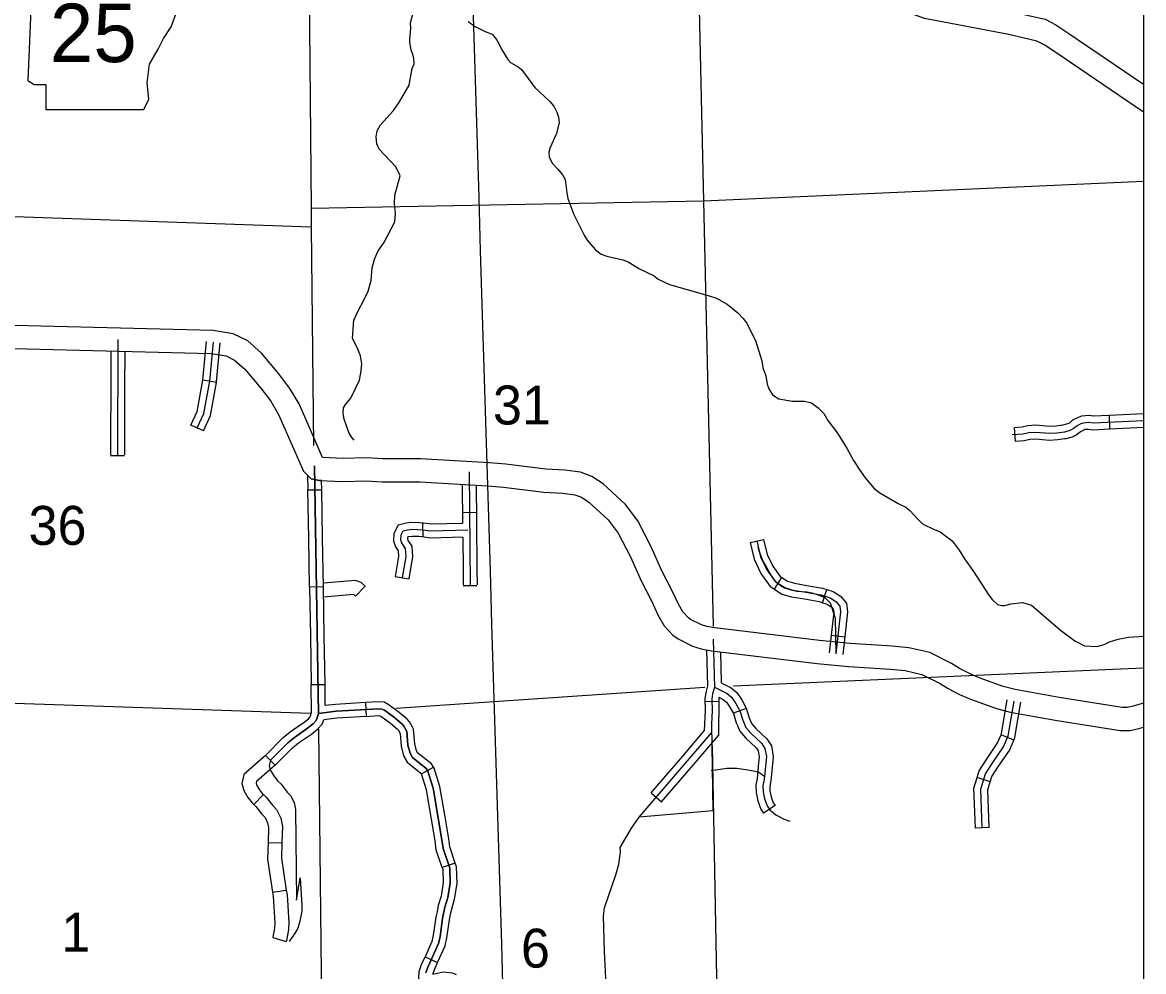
# Model space of a CAD drawing. Extents: x 1212896 to 1368412, y 378476 to 478763.
# Drawn here: x 1307154 to 1319317, y 403202 to 413498 of the extents above; entities that cross this region are included whole.
import ezdxf

# ---------------------------------------------------------------- set-up
doc = ezdxf.new("R2010")
doc.units = 0
for name, color, linetype in [('1', 7, 'Continuous'), ('Level 10', 7, 'Continuous'), ('Level 21', 7, 'Continuous'), ('Level 31', 7, 'Continuous'), ('Level 32', 7, 'Continuous'), ('Level 35', 7, 'Continuous'), ('Level 4', 7, 'Continuous'), ('Level 45', 7, 'Continuous'), ('Level 5', 7, 'Continuous'), ('Level 60', 7, 'Continuous')]:
    doc.layers.add(name, color=color, linetype=linetype)

msp = doc.modelspace()

# ---------------------------------------------------------------- linework, layer by layer
at = {"layer": '1'}
msp.add_lwpolyline([(1257400, 437504), (1319317, 437504), (1319317, 388319), (1257400, 388319)], close=True, dxfattribs=at)
at = {"layer": 'Level 10'}
for points in [[(1312881, 415815), (1314205, 414413), (1314294, 414326), (1314300, 414323), (1314959, 414335), (1315070, 414315), (1315316, 414244), (1316344, 414016), (1316809, 413855), (1317007, 413781), (1317906, 413611), (1318249, 413533), (1318366, 413471), (1318506, 413380), (1319317, 412828)], [(1319317, 412525), (1318367, 413172), (1318239, 413255), (1318161, 413296), (1317855, 413366), (1316940, 413540), (1316725, 413620), (1316276, 413775), (1315255, 414002), (1315013, 414071), (1314939, 414084), (1314254, 414072), (1314154, 414112), (1314027, 414238), (1312699, 415644)], [(1312217, 408722), (1311473, 408764), (1311065, 408764), (1310887, 408774), (1310631, 408767), (1310410, 408779), (1310156, 409360), (1310056, 409529), (1309937, 409686), (1309747, 409910), (1309598, 410045), (1309442, 410121), (1309225, 410157), (1306346, 410229), (1305872, 410234), (1302228, 410310)], [(1302110, 410062), (1305869, 409984), (1306341, 409979), (1309201, 409908), (1309365, 409880), (1309456, 409836), (1309567, 409736), (1309742, 409530), (1309848, 409390), (1309933, 409246), (1310203, 408629), (1310286, 408547), (1310378, 408530), (1310628, 408517), (1310884, 408524), (1311058, 408514), (1311466, 408514), (1312198, 408472)], [(1319317, 406113), (1319204, 406080), (1319143, 406067), (1319084, 406066), (1318400, 406176), (1317924, 406262), (1317793, 406295), (1317533, 406389), (1317429, 406434), (1317320, 406490), (1317232, 406545), (1316997, 406663), (1316772, 406715), (1316591, 406733), (1316135, 406762), (1315801, 406792), (1314667, 406930), (1314578, 406945), (1314520, 406964), (1314402, 407023), (1314379, 407040), (1314318, 407104), (1314270, 407186), (1314208, 407324), (1314090, 407550), (1313976, 407808), (1313830, 408091), (1313695, 408270), (1313454, 408493), (1313333, 408572), (1313208, 408619), (1313038, 408641), (1312833, 408651), (1312399, 408705), (1312217, 408722)], [(1312198, 408472), (1312372, 408456), (1312811, 408402), (1313016, 408391), (1313147, 408374), (1313219, 408348), (1313300, 408295), (1313509, 408101), (1313618, 407957), (1313750, 407700), (1313865, 407442), (1313983, 407215), (1314048, 407071), (1314117, 406953), (1314212, 406853), (1314269, 406810), (1314425, 406731), (1314519, 406702), (1314631, 406683), (1315775, 406543), (1316116, 406513), (1316571, 406484), (1316731, 406468), (1316912, 406426), (1317109, 406327), (1317196, 406273), (1317322, 406208), (1317441, 406156), (1317720, 406056), (1317871, 406018), (1318358, 405929), (1319065, 405816), (1319171, 405817), (1319265, 405838), (1319317, 405853)]]:
    msp.add_lwpolyline(points, dxfattribs=at)
at = {"layer": 'Level 21'}
for p, q in [((1307247, 413638), (1307213, 412868)), ((1308769, 413452), (1308820, 413587)), ((1308685, 413325), (1308769, 413452)), ((1308626, 413207), (1308685, 413325)), ((1308533, 413046), (1308626, 413207)), ((1308507, 412843), (1308533, 413046)), ((1307213, 412868), (1307281, 412826)), ((1307281, 412826), (1307408, 412826)), ((1307408, 412826), (1307408, 412555)), ((1308524, 412665), (1308507, 412843)), ((1308473, 412555), (1308524, 412665)), ((1307408, 412555), (1308473, 412555))]:
    msp.add_line(p, q, dxfattribs=at)
at = {"layer": 'Level 31'}
for p, q in [((1310251, 408427), (1310401, 408429)), ((1310419, 407374), (1310269, 407371)), ((1310269, 407371), (1310269, 407371)), ((1310287, 406315), (1310437, 406318)), ((1310875, 406121), (1310884, 405971)), ((1311252, 405784), (1311252, 405784)), ((1309897, 405441), (1309791, 405547)), ((1311483, 405346), (1311613, 405420)), ((1311850, 404380), (1311708, 404332)), ((1311522, 403362), (1311659, 403301))]:
    msp.add_line(p, q, dxfattribs=at)
for points in [[(1310367, 406002), (1310322, 408688)], [(1310248, 408584), (1310251, 408427)], [(1310399, 408529), (1310378, 408530), (1310286, 408547), (1310248, 408584)], [(1310401, 408429), (1310399, 408529)], [(1310260, 407899), (1310251, 408427)], [(1310410, 407902), (1310401, 408429)], [(1310269, 407371), (1310260, 407899)], [(1310419, 407374), (1310410, 407902)], [(1310269, 407371), (1310278, 406843)], [(1310428, 406846), (1310419, 407374)], [(1310278, 406843), (1310287, 406315)], [(1310437, 406318), (1310428, 406846)], [(1310196, 405897), (1310257, 405944), (1310275, 405964), (1310292, 406014), (1310287, 406315)], [(1310440, 406087), (1310437, 406318)], [(1311382, 405860), (1311353, 405910), (1311327, 405940), (1311241, 406014), (1311121, 406101), (1311077, 406123), (1311022, 406130), (1310875, 406121)], [(1311532, 403189), (1311554, 403250), (1311667, 403505), (1311686, 403584), (1311713, 403778), (1311738, 403900), (1311770, 404006), (1311794, 404162), (1311790, 404324), (1311718, 404538), (1311706, 404630), (1311610, 405191), (1311552, 405377), (1311535, 405406), (1311385, 405523), (1311359, 405570), (1311337, 405660), (1311325, 405808), (1311291, 405866), (1311273, 405887), (1311195, 405955), (1311082, 406037), (1311055, 406050), (1311019, 406054), (1310557, 406026), (1310367, 406002)], [(1310875, 406121), (1310550, 406101), (1310440, 406087)], [(1309791, 405547), (1309984, 405740), (1310060, 405803), (1310190, 405892), (1310196, 405897)], [(1309844, 405494), (1310034, 405685), (1310105, 405743), (1310234, 405831), (1310308, 405889), (1310341, 405925), (1310367, 406002)], [(1310289, 405778), (1310360, 405834), (1310407, 405887), (1310423, 405934)], [(1310884, 405971), (1310564, 405951), (1310423, 405934)], [(1310884, 405971), (1311017, 405979), (1311033, 405977), (1311043, 405972), (1311148, 405896), (1311220, 405835), (1311230, 405823), (1311252, 405784)], [(1309897, 405441), (1310085, 405629), (1310151, 405683), (1310278, 405770), (1310289, 405778)], [(1311252, 405784), (1311252, 405785), (1311263, 405649), (1311288, 405542), (1311328, 405473), (1311477, 405356), (1311483, 405346)], [(1311613, 405420), (1311593, 405456), (1311443, 405573), (1311429, 405598), (1311411, 405672), (1311398, 405831), (1311382, 405860)], [(1311739, 404882), (1311683, 405209), (1311621, 405407), (1311613, 405420)], [(1311591, 404857), (1311537, 405174), (1311482, 405347), (1311483, 405346)], [(1311708, 404332), (1311644, 404521), (1311632, 404619), (1311591, 404857)], [(1311850, 404380), (1311791, 404555), (1311780, 404641), (1311739, 404882)], [(1311708, 404332), (1311715, 404311), (1311719, 404167), (1311697, 404022), (1311665, 403919), (1311652, 403852)], [(1311799, 403823), (1311811, 403882), (1311843, 403989), (1311870, 404158), (1311865, 404337), (1311850, 404380)], [(1311652, 403852), (1311640, 403791), (1311612, 403598), (1311596, 403528), (1311522, 403362)], [(1311659, 403301), (1311739, 403481), (1311759, 403570), (1311787, 403765), (1311799, 403823)], [(1311801, 403030), (1311779, 403040), (1311727, 403046), (1311637, 403023), (1311555, 403028), (1311490, 403060), (1311455, 403126), (1311458, 403203), (1311485, 403278), (1311522, 403362)], [(1311864, 403166), (1311820, 403186), (1311717, 403197), (1311622, 403174), (1311607, 403175), (1311624, 403222), (1311659, 403301)]]:
    msp.add_lwpolyline(points, dxfattribs=at)
at = {"layer": 'Level 32'}
for p, q in [((1309259, 409593), (1309111, 409619)), ((1309119, 409068), (1308983, 409131)), ((1315049, 407857), (1315195, 407891)), ((1315312, 407350), (1315393, 407476)), ((1315834, 407204), (1315880, 407347)), ((1315927, 406852), (1316076, 406835)), ((1317909, 405712), (1317771, 405771)), ((1317654, 405262), (1317511, 405307)), ((1309664, 405014), (1309768, 405122)), ((1317643, 404765), (1317493, 404758)), ((1309819, 404601), (1309969, 404597)), ((1309869, 404064), (1310017, 404086)), ((1309872, 403572), (1310015, 403527))]:
    msp.add_line(p, q, dxfattribs=at)
for points in [[(1309051, 409100), (1309123, 409255), (1309186, 409608), (1309227, 410030)], [(1309111, 409618), (1309152, 410037)], [(1309259, 409593), (1309260, 409598), (1309301, 410023)], [(1308983, 409131), (1309051, 409278), (1309111, 409619)], [(1309119, 409068), (1309196, 409233), (1309259, 409593)], [(1310322, 408688), (1310367, 406002), (1310341, 405925), (1310308, 405889), (1310234, 405831), (1310105, 405743), (1310034, 405685), (1309844, 405494), (1309830, 405437), (1309843, 405389), (1309882, 405324), (1309920, 405273), (1309960, 405235), (1310028, 405148), (1310067, 405107), (1310104, 405032), (1310117, 404962), (1310128, 403977), (1310169, 404218), (1310186, 403924), (1310184, 403857), (1310164, 403748), (1310141, 403674), (1310118, 403629), (1310047, 403527)], [(1315049, 407857), (1315091, 407675), (1315166, 407522), (1315267, 407379), (1315312, 407350)], [(1315122, 407874), (1315162, 407701), (1315231, 407561), (1315320, 407434), (1315424, 407367), (1315513, 407341), (1315653, 407318), (1315815, 407289), (1315917, 407256), (1315979, 407216), (1316023, 407165), (1316031, 407104), (1315980, 406650)], [(1315195, 407891), (1315233, 407726), (1315296, 407599), (1315373, 407489), (1315393, 407476)], [(1315393, 407476), (1315456, 407436), (1315530, 407414), (1315665, 407392), (1315833, 407362), (1315880, 407347)], [(1315312, 407350), (1315393, 407298), (1315496, 407267), (1315640, 407244), (1315797, 407217), (1315834, 407204)], [(1315880, 407347), (1315950, 407324), (1316029, 407273), (1316094, 407197), (1316107, 407105), (1316076, 406835)], [(1315834, 407204), (1315885, 407188), (1315929, 407159), (1315951, 407133), (1315956, 407102), (1315927, 406852)], [(1315927, 406852), (1315905, 406659)], [(1316076, 406835), (1316054, 406642)], [(1317568, 404761), (1317551, 405182), (1317603, 405349), (1317682, 405472), (1317796, 405639), (1317849, 405761), (1317913, 406137)], [(1317771, 405771), (1317776, 405783), (1317839, 406150)], [(1310367, 406002), (1310557, 406026), (1311019, 406054), (1311055, 406050), (1311082, 406037), (1311195, 405955), (1311273, 405887), (1311291, 405866), (1311325, 405808), (1311337, 405660), (1311359, 405570), (1311385, 405523), (1311535, 405406), (1311552, 405377), (1311610, 405191), (1311706, 404630), (1311718, 404538), (1311790, 404324), (1311794, 404162), (1311770, 404006), (1311738, 403900), (1311713, 403778), (1311686, 403584), (1311667, 403505), (1311554, 403250), (1311532, 403189)], [(1317909, 405712), (1317921, 405740), (1317987, 406125)], [(1317511, 405307), (1317535, 405381), (1317620, 405513), (1317730, 405675), (1317771, 405771)], [(1317654, 405262), (1317672, 405317), (1317745, 405430), (1317862, 405602), (1317909, 405712)], [(1309791, 405547), (1309557, 405340), (1309534, 405244), (1309555, 405168), (1309601, 405091), (1309645, 405033), (1309664, 405014)], [(1309897, 405441), (1309693, 405263), (1309689, 405246), (1309694, 405228), (1309726, 405175), (1309758, 405132), (1309768, 405122)], [(1317493, 404758), (1317475, 405192), (1317511, 405307)], [(1317643, 404765), (1317626, 405172), (1317654, 405262)], [(1309768, 405122), (1309797, 405094), (1309866, 405007), (1309911, 404960), (1309957, 404865), (1309974, 404777), (1309969, 404597)], [(1309664, 405014), (1309686, 404993), (1309752, 404908), (1309786, 404873), (1309814, 404817), (1309824, 404764), (1309819, 404601)], [(1309819, 404601), (1309814, 404422), (1309869, 404064)], [(1309969, 404597), (1309965, 404431), (1310017, 404086)], [(1309869, 404064), (1309876, 404019), (1309892, 403731), (1309890, 403674), (1309872, 403574), (1309872, 403572)], [(1310017, 404086), (1310025, 404034), (1310043, 403733), (1310040, 403657), (1310018, 403538), (1310015, 403527)]]:
    msp.add_lwpolyline(points, dxfattribs=at)
at = {"layer": 'Level 35'}
for points in [[(1310753, 408966), (1310727, 408996), (1310695, 409050), (1310646, 409193), (1310634, 409257), (1310638, 409317), (1310659, 409353), (1310718, 409421), (1310812, 409617), (1310830, 409719), (1310835, 409796), (1310823, 409882), (1310785, 409973), (1310736, 410068), (1310749, 410269), (1310799, 410378), (1310856, 410478), (1310904, 410582), (1310939, 410698), (1310947, 410836), (1310972, 410931), (1311015, 411019), (1311074, 411108), (1311196, 411336), (1311202, 411425), (1311192, 411535), (1311193, 411624), (1311252, 411834), (1311205, 411933), (1311023, 412125), (1311000, 412181), (1310992, 412258), (1311004, 412322), (1311039, 412388), (1311180, 412543), (1311246, 412638), (1311351, 412819), (1311383, 412999), (1311403, 413048), (1311401, 413111), (1311391, 413149), (1311371, 413197), (1311358, 413281), (1311357, 413313), (1311367, 413436), (1311366, 413495), (1311394, 413604)], [(1312052, 413460), (1311989, 413503)], [(1312052, 413460), (1312175, 413399), (1312252, 413371), (1312297, 413313), (1312327, 413264), (1312353, 413209), (1312422, 413096), (1312450, 413065), (1312531, 413017), (1312569, 412987), (1312713, 412792), (1312876, 412640), (1312920, 412590), (1312953, 412526), (1312970, 412472), (1312976, 412414), (1312948, 412294), (1312880, 412141), (1312866, 412090), (1312869, 412042), (1312902, 411973), (1312964, 411907), (1313013, 411845), (1313042, 411793), (1313060, 411651), (1313073, 411589), (1313138, 411413), (1313249, 411189), (1313281, 411138), (1313321, 411088), (1313372, 411031), (1313432, 410984), (1313494, 410963), (1313668, 410923), (1313726, 410900), (1313850, 410826), (1314008, 410749), (1314051, 410714), (1314175, 410654), (1314595, 410536), (1314685, 410506), (1314800, 410443), (1314916, 410349), (1314975, 410287), (1315008, 410240), (1315106, 410048), (1315176, 409826), (1315188, 409751), (1315218, 409663), (1315235, 409574), (1315251, 409523), (1315293, 409460), (1315361, 409415), (1315508, 409390), (1315638, 409391), (1315716, 409373), (1315786, 409318)], [(1315786, 409318), (1315849, 409255), (1315891, 409180), (1315997, 409043), (1316103, 408874), (1316172, 408745), (1316246, 408631), (1316297, 408557), (1316395, 408444), (1316457, 408394), (1316654, 408278), (1316738, 408239), (1316781, 408204), (1316867, 408109), (1316917, 408064), (1316942, 408047), (1317031, 408005), (1317112, 407974), (1317240, 407873), (1317315, 407775), (1317374, 407680), (1317471, 407542), (1317640, 407287), (1317675, 407240), (1317731, 407184), (1317779, 407175), (1317813, 407175), (1317877, 407191), (1318002, 407205), (1318103, 407177), (1318416, 406906), (1318570, 406791), (1318676, 406734), (1318809, 406728), (1318890, 406750), (1318947, 406780), (1319041, 406808), (1319155, 406831), (1319317, 406842)]]:
    msp.add_lwpolyline(points, dxfattribs=at)
at = {"layer": 'Level 4'}
for points in [[(1310238, 416601), (1310285, 411481), (1310286, 411278), (1310312, 408908)], [(1319317, 406493), (1314869, 406297)], [(1314557, 406283), (1311204, 406057)], [(1306534, 406131), (1310280, 406004)], [(1310367, 405830), (1310419, 400869)]]:
    msp.add_lwpolyline(points, dxfattribs=at)
at = {"layer": 'Level 45'}
for p, q in [((1318953, 409086), (1318946, 409235)), ((1317929, 408952), (1317918, 409102)), ((1308260, 408798), (1308110, 408798)), ((1312080, 408181), (1311930, 408179)), ((1311493, 408065), (1311498, 407918)), ((1311346, 407459), (1311198, 407483)), ((1310871, 407384), (1310768, 407275)), ((1312085, 407388), (1311935, 407387)), ((1314705, 406129), (1314562, 406132)), ((1315006, 406056), (1314870, 406004)), ((1313974, 405140), (1314088, 405042)), ((1315320, 405003), (1315195, 404920))]:
    msp.add_line(p, q, dxfattribs=at)
for points in [[(1308191, 410058), (1308186, 408809)], [(1308114, 409935), (1308113, 409530)], [(1308264, 409931), (1308263, 409530)], [(1308113, 409530), (1308110, 409002)], [(1308263, 409530), (1308260, 409002)], [(1319317, 409176), (1318769, 409151), (1318722, 409157), (1318690, 409156), (1318662, 409153), (1318638, 409144), (1318591, 409119), (1318555, 409088), (1318517, 409071), (1318458, 409054), (1318378, 409042), (1318299, 409038), (1318144, 409051), (1318072, 409047), (1318012, 409032), (1317891, 409023)], [(1318946, 409235), (1318772, 409227), (1318726, 409234), (1318684, 409232), (1318645, 409228), (1318607, 409214), (1318548, 409182), (1318514, 409153), (1318491, 409143), (1318442, 409129), (1318436, 409128)], [(1319317, 409253), (1318946, 409235)], [(1318436, 409128), (1318370, 409118), (1318300, 409114), (1318145, 409128), (1318061, 409122), (1318000, 409108), (1317918, 409102)], [(1318953, 409086), (1318765, 409077), (1318718, 409084), (1318696, 409083), (1318680, 409081), (1318668, 409077), (1318633, 409058), (1318595, 409026), (1318542, 409001), (1318473, 408982), (1318459, 408980)], [(1319317, 409103), (1318953, 409086)], [(1308110, 409002), (1308110, 408809)], [(1308260, 409002), (1308260, 408809)], [(1318459, 408980), (1318386, 408969), (1318297, 408964), (1318143, 408977), (1318083, 408973), (1318023, 408959), (1317929, 408952)], [(1312001, 408624), (1312013, 407397)], [(1311926, 408488), (1311930, 408064)], [(1312076, 408479), (1312080, 408096)], [(1311930, 408095), (1311930, 408075)], [(1312080, 408096), (1312085, 407568)], [(1311461, 408069), (1311380, 408072), (1311319, 408068), (1311230, 408045), (1311183, 407956), (1311179, 407876), (1311200, 407811), (1311231, 407765), (1311235, 407709), (1311228, 407663)], [(1311986, 407989), (1311586, 407979), (1311499, 407992), (1311381, 407996), (1311331, 407992), (1311282, 407980), (1311258, 407935), (1311256, 407886), (1311269, 407845), (1311305, 407791), (1311312, 407705), (1311274, 407474)], [(1311930, 408064), (1311590, 408055), (1311506, 408068), (1311461, 408069)], [(1311456, 407920), (1311383, 407922), (1311343, 407919), (1311331, 407916), (1311331, 407915), (1311330, 407896), (1311336, 407878), (1311377, 407817), (1311386, 407702), (1311376, 407639)], [(1311931, 407914), (1311581, 407905), (1311492, 407918), (1311456, 407920)], [(1311931, 407914), (1311935, 407567)], [(1315133, 407810), (1315143, 407770), (1315178, 407671), (1315280, 407491), (1315318, 407442), (1315385, 407387), (1315421, 407365), (1315479, 407347), (1315556, 407330), (1315664, 407321), (1315718, 407311), (1315788, 407288), (1315861, 407259), (1315916, 407202), (1315973, 407036), (1315980, 406650)], [(1311228, 407663), (1311198, 407487)], [(1311376, 407639), (1311346, 407462)], [(1311935, 407567), (1311936, 407396)], [(1312085, 407568), (1312086, 407398)], [(1310871, 407384), (1310829, 407423), (1310766, 407444), (1310420, 407414)], [(1310768, 407275), (1310751, 407291), (1310748, 407292), (1310422, 407264)], [(1314649, 406807), (1314663, 406288), (1314642, 406216), (1314634, 406158), (1314637, 406035), (1314631, 405886), (1314645, 404947), (1313845, 404876)], [(1314576, 406692), (1314587, 406298)], [(1314726, 406671), (1314736, 406334)], [(1314587, 406301), (1314567, 406231), (1314558, 406162), (1314561, 406036), (1314552, 405814)], [(1314663, 406288), (1314801, 406219), (1314848, 406178), (1314895, 406112), (1314938, 406031), (1314970, 405928), (1315004, 405849), (1315057, 405787), (1315174, 405680), (1315210, 405623), (1315225, 405534), (1315200, 405286), (1315188, 405220), (1315190, 405153), (1315205, 405076), (1315234, 404999), (1315265, 404953), (1315329, 404901), (1315417, 404856), (1315479, 404833)], [(1314736, 406334), (1314842, 406281), (1314903, 406228), (1314958, 406150), (1315006, 406060), (1315040, 405954), (1315050, 405928)], [(1314708, 406180), (1314711, 406034), (1314705, 405885), (1314707, 405763)], [(1314708, 406180), (1314758, 406155), (1314791, 406126), (1314830, 406071), (1314867, 406001), (1314899, 405902), (1314912, 405870)], [(1315050, 405928), (1315067, 405889), (1315110, 405838), (1315231, 405728), (1315280, 405650), (1315299, 405536), (1315291, 405452)], [(1313639, 404549), (1313761, 404759), (1313845, 404876), (1314634, 405796)], [(1314318, 405540), (1314552, 405814)], [(1314432, 405443), (1314707, 405763)], [(1314912, 405870), (1314938, 405809), (1315002, 405734), (1315115, 405630), (1315137, 405596), (1315148, 405531), (1315141, 405467)], [(1313974, 405140), (1314318, 405540)], [(1314088, 405042), (1314432, 405443)], [(1314626, 405382), (1314795, 405410), (1314904, 405407), (1315025, 405392), (1315086, 405380), (1315142, 405364), (1315209, 405318)], [(1315141, 405467), (1315124, 405297), (1315111, 405226), (1315113, 405145), (1315131, 405055), (1315166, 404964), (1315195, 404920)], [(1315291, 405452), (1315273, 405275), (1315262, 405214), (1315263, 405161), (1315276, 405097), (1315300, 405033), (1315320, 405003)], [(1313727, 402330), (1313469, 402354), (1313425, 402427), (1313453, 402681), (1313480, 403002), (1313483, 403130), (1313468, 403420), (1313458, 403807), (1313470, 403892), (1313593, 404250), (1313623, 404367), (1313643, 404499), (1313639, 404550)]]:
    msp.add_lwpolyline(points, dxfattribs=at)
at = {"layer": 'Level 5'}
for points in [[(1314408, 418927), (1314422, 416850), (1314542, 411559), (1314649, 406950)], [(1319317, 411772), (1314542, 411559)], [(1310286, 411278), (1304990, 411462), (1302718, 411522)], [(1314542, 411559), (1310285, 411481)], [(1314636, 405652), (1314725, 401003)]]:
    msp.add_lwpolyline(points, dxfattribs=at)
at = {"layer": 'Level 60'}
msp.add_spline([(1312810, 388462), (1311686, 425481), (1311316, 437640)], degree=3, dxfattribs=at)

# ---------------------------------------------------------------- texts
at = {"layer": 'Level 21'}
msp.add_text('25', height=633.6, dxfattribs=at).set_placement((1307452, 413068))
at = {"layer": 'Level 5'}
for s, height, p in [('31', 422.4, (1312259, 409137)), ('36', 422.4, (1307221, 407831)), ('1', 422, (1307577, 403418)), ('6', 422, (1312563, 403245))]:
    msp.add_text(s, height=height, dxfattribs=at).set_placement(p)

doc.saveas('drawing.dxf')
